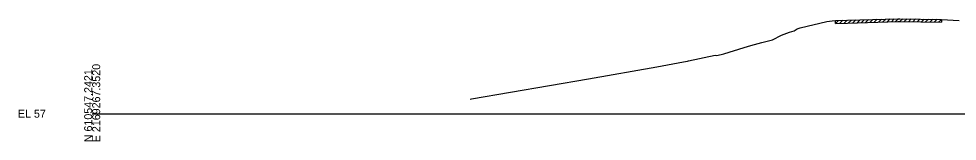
# Model space of a CAD drawing. Extents: x -26 to 6803, y -10 to 19606.
# Drawn here: x 1974.3 to 2302.7, y 9990.3 to 10033.3 of the extents above; entities that cross this region are included whole.
import ezdxf

# ---------------------------------------------------------------- set-up
doc = ezdxf.new("R2010")
doc.units = 0
for name, color, linetype in [('RD_GPK_XS_Cell', 7, 'Continuous'), ('RD_XS_ExGround', 7, 'Continuous'), ('RD_XS_ExPaveRet', 7, 'Continuous')]:
    doc.layers.add(name, color=color, linetype=linetype)

msp = doc.modelspace()

# ---------------------------------------------------------------- linework, layer by layer
at = {"layer": 'RD_GPK_XS_Cell'}
msp.add_line((2000, 10000), (2400, 10000), dxfattribs=at)
at = {"layer": 'RD_XS_ExGround'}
msp.add_lwpolyline([(2132.24, 10005.07), (2132.66, 10005.19), (2173.61, 10012.23), (2197.56, 10016.47), (2206.93, 10018.21), (2208.26, 10018.45), (2208.67, 10018.54), (2217.97, 10020.51), (2218.49, 10020.47), (2221.03, 10020.98), (2228.09, 10023.23), (2230.5, 10023.99), (2234.35, 10025.04), (2238, 10025.97), (2241.23, 10027.51), (2243.92, 10028.56), (2245.65, 10029.12), (2246.65, 10029.8), (2247.7, 10030.11), (2257, 10032.31), (2258.85, 10032.54), (2260.11, 10032.7), (2264.23, 10032.82), (2281.82, 10033.34), (2282.58, 10033.33), (2297.13, 10033.1), (2303.37, 10032.67)], dxfattribs=at)
at = {"layer": 'RD_XS_ExPaveRet'}
for p, q in [((2260.11, 10031.7), (2261.15, 10032.73)), ((2260.11, 10031.7), (2260.11, 10032.7)), ((2260.11, 10031.7), (2264.23, 10031.82)), ((2261.61, 10031.75), (2262.65, 10032.78)), ((2263.11, 10031.79), (2264.15, 10032.82)), ((2264.23, 10031.82), (2281.82, 10032.34)), ((2264.61, 10031.84), (2265.65, 10032.87)), ((2266.11, 10031.88), (2267.15, 10032.91)), ((2267.61, 10031.92), (2268.65, 10032.95)), ((2269.11, 10031.97), (2270.15, 10033)), ((2270.61, 10032.01), (2271.65, 10033.04)), ((2272.11, 10032.06), (2273.15, 10033.09)), ((2273.61, 10032.1), (2274.65, 10033.13)), ((2275.11, 10032.14), (2276.15, 10033.17)), ((2276.61, 10032.19), (2277.65, 10033.22)), ((2278.11, 10032.23), (2279.15, 10033.26)), ((2279.61, 10032.28), (2280.65, 10033.31)), ((2281.11, 10032.32), (2282.13, 10033.34)), ((2281.82, 10032.34), (2282.58, 10032.33)), ((2282.58, 10032.33), (2297.13, 10032.1)), ((2282.61, 10032.33), (2283.6, 10033.31)), ((2284.11, 10032.31), (2285.1, 10033.29)), ((2285.61, 10032.28), (2286.6, 10033.27)), ((2287.11, 10032.26), (2288.1, 10033.24)), ((2288.61, 10032.24), (2289.6, 10033.22)), ((2290.11, 10032.21), (2291.1, 10033.2)), ((2291.61, 10032.19), (2292.6, 10033.17)), ((2293.11, 10032.17), (2294.1, 10033.15)), ((2294.61, 10032.14), (2295.6, 10033.13)), ((2296.11, 10032.12), (2297.1, 10033.1)), ((2297.13, 10033.1), (2297.13, 10032.1)), ((2297.13, 10032.1), (2297.13, 10032.1))]:
    msp.add_line(p, q, dxfattribs=at)

# ---------------------------------------------------------------- texts
at = {"layer": 'RD_GPK_XS_Cell'}
for s, p in [('N 610547.2421', (2000, 9990)), ('E 2169267.3520', (2002.8, 9990))]:
    msp.add_text(s, height=2.8, rotation=90, dxfattribs=at).set_placement(p)
msp.add_text('EL 57', height=2.8, dxfattribs=at).set_placement((1974, 9998.6))

doc.saveas('drawing.dxf')
